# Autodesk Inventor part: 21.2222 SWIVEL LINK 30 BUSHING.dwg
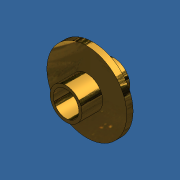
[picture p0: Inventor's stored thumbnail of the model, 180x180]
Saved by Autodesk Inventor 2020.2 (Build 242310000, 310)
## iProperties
Part Number: 21.2222 SWIVEL LINK 30 BUSHING.dwg
Material: Bronze, Cast
Document SubType Name: Modeling
Designer: amoles
Appearance: Bronze - Satin
Mass: 11.0767 g
Surface Area: 18.2369 cm^2
Volume: 1.24878 cm^3
Density: 8.87 g/cm^3
Author: amoles
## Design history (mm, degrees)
feature "Base1"
body "Solid1"
